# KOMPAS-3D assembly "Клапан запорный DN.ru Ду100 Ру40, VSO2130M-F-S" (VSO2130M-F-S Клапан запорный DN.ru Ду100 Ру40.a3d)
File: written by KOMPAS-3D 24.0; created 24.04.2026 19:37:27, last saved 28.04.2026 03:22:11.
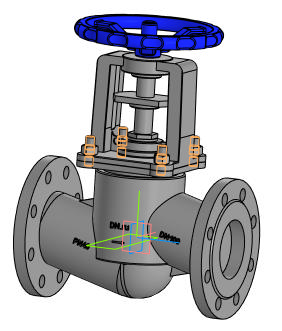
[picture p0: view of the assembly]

Document properties: Автор: DN.ru; Полное имя файла: C:\Работа\ГОТОВЫЕ ИСХОДНИКИ\VSO2130M-F-S Клапан запорный сильфонный DN.ru Ду15-100 Ру40\исходные материалы\DN100\VSO2130M-F-S Клапан запорный DN.ru Ду100 Ру40.a3d

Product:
- Component [detail]: Корпус  | qty 1  | pos. 1  | Масса: 6.9; Автор: R2D2; source file: Korpus.m3d
- Component [detail]: Деталь  | qty 1  | pos. 2  | Масса: 9.446861; Автор: mrdid; source file: rama.m3d
- Component [detail]: Деталь2  | qty 1  | pos. 3  | Масса: 3.344958; Автор: R2D2; additional columns: Типовые; source file: shturval.m3d
- Component [standard]: Шпилька М16-6gx35 ГОСТ 22032-76  | qty 4  | Масса: 0.07017; Раздел спецификации: Стандартные изделия; Рассекать на разрезах: no
- Component [standard]: Гайка М16-6H ГОСТ 5915-70  | qty 4  | Масса: 0.03761; Раздел спецификации: Стандартные изделия; Рассекать на разрезах: no
- Part/product: Клапан запорный DN.ru Ду100 Ру40  | designation VSO2130M-F-S
    Масса: 35
    Раздел спецификации: Прочие изделия
    Примечание: D090-01978

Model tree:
1. Контекстная связь:1  (with: Эскиз:2, Ребро.Элемент выдавливания:14, Контекстная связь (Деталь):1)
2. Контекстная связь:2  (with: Контекстная связь (Деталь):2)
3. Массив по концентрической сетке:1  (with: Грань.Элемент выдавливания:1, Грань.Элемент выдавливания:15, Грань.Элемент выдавливания:3, Грань.Элемент выдавливания:16, Грань.Элемент выдавливания:2, Грань.Элемент выдавливания:17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)  (labels: Грань.Твердое тело1)  (4 pattern instances)
     Шаг 2 = 360; Угол = 8

Referenced files in C:\Работа\ГОТОВЫЕ ИСХОДНИКИ\VSO2130M-F-S Клапан запорный сильфонный DN.ru Ду15-100 Ру40\исходные материалы\DN100\: Korpus.m3d, rama.m3d, shturval.m3d
Referenced files in C:\Program Files\ASCON\KOMPAS-3D v24\Libs\PolynomLib\DATA\vault\Methods\Kompas\3D\: PLib_Stud_1_900.m3d, PLib_Nut_OST92_900.m3d
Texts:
  Крепежное изделие ГОСТ
  BOSimple***PART:d7cea355-acbb-e7a9-246f-9517ee95b2f8***SHORTLOC:Root±30±20±10±120±10±20[Нет;Без покрытия;Без указания материала;-;16;35;2;2]
  BOSimple***PART:17b45fe1-43c8-f41a-5df4-ae57481e6c3b***SHORTLOC:Root±30±10±20±©{}110±10±50±60[Нет;Без покрытия;Без указания материала;-;16;2;24]
  Программные изделия  и базы данных
  VSO2130M-F-S
  Деталь2 Деталь2
  Шпилька М16-6gx35 ГОСТ 22032-76 (1)
  cut1
  Гайка М16-6H ГОСТ 5915-70 (1)
  bcut1
  hole1
  hcut1
  hole2
  Гайка М16-6H ГОСТ 5915-70 (2)
  Шпилька М16-6gx35 ГОСТ 22032-76 (2)
  Гайка М16-6H ГОСТ 5915-70 (3)
  Шпилька М16-6gx35 ГОСТ 22032-76 (3)
  Гайка М16-6H ГОСТ 5915-70 (4)
  Шпилька М16-6gx35 ГОСТ 22032-76 (4)
  Плоскость XY.Начало координат
  Plane. Начало координат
